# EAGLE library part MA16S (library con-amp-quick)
AMP QUICK CONNECTOR
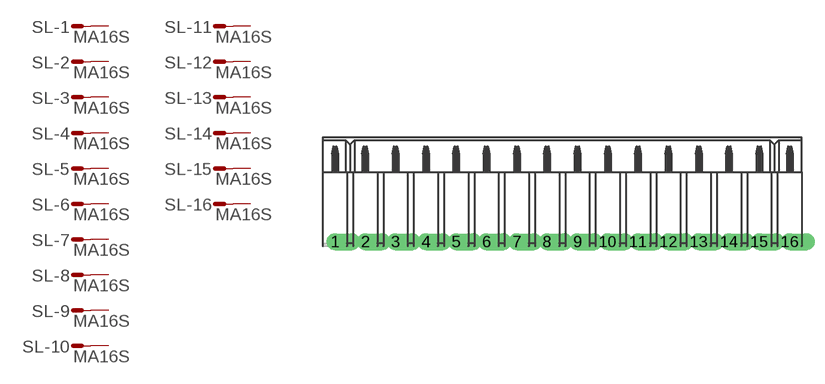
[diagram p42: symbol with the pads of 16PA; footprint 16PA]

Designator prefix SL; gates -1=M -2=M -3=M -4=M -5=M -6=M -7=M -8=M -9=M -10=M -11=M -12=M -13=M -14=M -15=M -16=M

## MA16S  [16PA]
1  -1:S  pas
2  -2:S  pas
3  -3:S  pas
4  -4:S  pas
5  -5:S  pas
6  -6:S  pas
7  -7:S  pas
8  -8:S  pas
9  -9:S  pas
10  -10:S  pas
11  -11:S  pas
12  -12:S  pas
13  -13:S  pas
14  -14:S  pas
15  -15:S  pas
16  -16:S  pas

## Footprint 16PA (pad centres in mm)
AMP QUICK CONNECTOR
drill 0.914 offset: 1 -19.05,0; 2 -16.51,0; 3 -13.97,0; 4 -11.43,0; 5 -8.89,0; 6 -6.35,0; 7 -3.81,0; 8 -1.27,0; 9 1.27,0; 10 3.81,0; 11 6.35,0; 12 8.89,0; 13 11.43,0; 14 13.97,0; 15 16.51,0; 16 19.05,0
